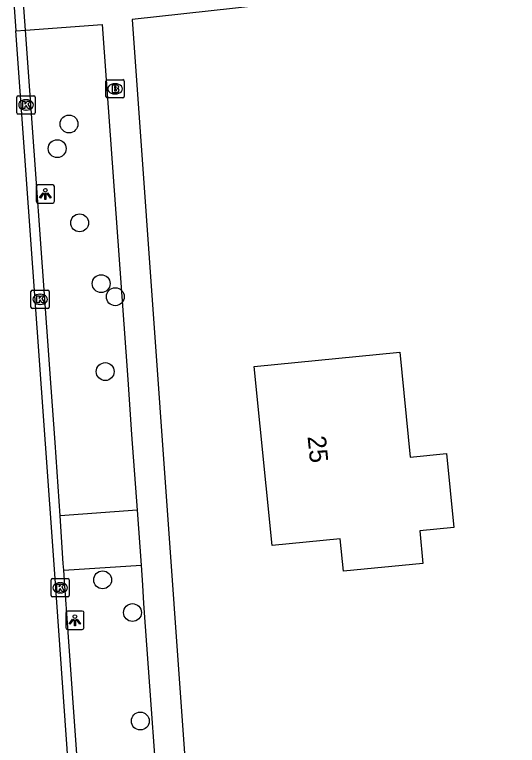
# Model space of a CAD drawing. Extents: x 162675 to 163482, y 379761 to 381227.
# Drawn here: x 163035.64 to 163063.15, y 380547.27 to 380587.25 of the extents above; entities that cross this region are included whole.
import ezdxf

# ---------------------------------------------------------------- set-up
doc = ezdxf.new("R2010")
doc.units = 0
for name, color, linetype in [('IMGEO_Boom', 7, 'Continuous'), ('IMGEO_Brandkraan', 7, 'Continuous'), ('IMGEO_Kolk', 7, 'Continuous'), ('IMGEO_Lichtpunt', 7, 'Continuous'), ('IMGEO_Pand', 7, 'Continuous'), ('IMGEO_Pand_nummerreeks', 7, 'Continuous'), ('IMGEO_Rijbaan_lokaal_gesloten', 7, 'Continuous'), ('IMGEO_Rijbaan_lokaal_open', 7, 'Continuous'), ('IMGEO_Voetpad_open', 7, 'Continuous')]:
    doc.layers.add(name, color=color, linetype=linetype)

msp = doc.modelspace()

# ---------------------------------------------------------------- linework, layer by layer
at = {"layer": 'IMGEO_Boom'}
for centre in [(163038.615, 380581.27), (163037.97, 380579.92), (163039.195, 380575.86), (163040.374, 380572.534), (163041.148, 380571.818), (163040.597, 380567.724), (163040.456, 380556.328), (163042.088, 380554.54), (163042.515, 380548.606)]:
    msp.add_circle(centre, 0.489, dxfattribs=at)
at = {"layer": 'IMGEO_Brandkraan'}
for p, q in [((163040.635, 380582.767), (163040.635, 380583.619)), ((163040.71, 380583.693), (163041.562, 380583.693)), ((163041.123, 380583.473), (163041.148, 380583.473)), ((163041.636, 380583.619), (163041.636, 380582.767)), ((163041.146, 380582.913), (163041.121, 380582.913)), ((163041.562, 380582.693), (163040.71, 380582.693))]:
    msp.add_line(p, q, dxfattribs=at)
for points in [[(163040.635, 380582.767), (163040.635, 380583.619)], [(163040.71, 380583.693), (163041.562, 380583.693)], [(163040.983, 380583.393), (163040.983, 380582.993), (163041.196, 380582.993)], [(163041.214, 380583.393), (163040.983, 380583.393)], [(163041.162, 380583.312), (163041.108, 380583.312), (163041.108, 380583.236)], [(163041.636, 380583.619), (163041.636, 380582.767)], [(163041.108, 380583.236), (163041.161, 380583.236)], [(163041.17, 380583.16), (163041.108, 380583.16), (163041.108, 380583.079)], [(163041.108, 380583.079), (163041.17, 380583.079)], [(163041.562, 380582.693), (163040.71, 380582.693)]]:
    msp.add_lwpolyline(points, dxfattribs=at)
for centre, radius, start, end in [((163040.712, 380583.617), 0.0765, 91.552, 178.448), ((163040.712, 380583.617), 0.0765, 91.552, 178.448), ((163041.163, 380583.274), 0.0379, 267.8285, 90.9355), ((163041.218, 380583.248), 0.145, 59.4692, 91.5367), ((163041.243, 380583.295), 0.0922, 285.5137, 58.1501), ((163041.56, 380583.617), 0.0765, 1.552, 88.448), ((163041.56, 380583.617), 0.0765, 1.552, 88.448), ((163041.171, 380583.119), 0.0404, 269.8759, 90.5077), ((163041.202, 380583.244), 0.251, 268.6676, 293.5347), ((163041.248, 380583.103), 0.105, 301.3115, 78.989), ((163040.712, 380582.769), 0.0765, 181.552, 268.448), ((163040.712, 380582.769), 0.0765, 181.552, 268.448), ((163041.56, 380582.769), 0.0765, 271.552, 358.448), ((163041.56, 380582.769), 0.0765, 271.552, 358.448)]:
    msp.add_arc(centre, radius, start, end, dxfattribs=at)
for centre, major_axis, ratio, start_param, end_param in [((163041.122, 380583.193), (-0.387, 0.002), 0.722429, 4.712389, 7.853982), ((163041.147, 380583.193), (-0.39, 0.002), 0.717154, 1.570796, 4.712389)]:
    msp.add_ellipse(centre, major_axis=major_axis, ratio=ratio, start_param=start_param, end_param=end_param, dxfattribs=at)
at = {"layer": 'IMGEO_Kolk'}
for p, q in [((163035.762, 380581.887), (163035.762, 380582.739)), ((163035.837, 380582.813), (163036.689, 380582.813)), ((163036.25, 380582.593), (163036.275, 380582.593)), ((163036.763, 380582.739), (163036.763, 380581.887)), ((163036.689, 380581.813), (163035.837, 380581.813)), ((163036.273, 380582.033), (163036.248, 380582.033)), ((163036.609, 380572.176), (163037.461, 380572.176)), ((163036.534, 380571.25), (163036.534, 380572.102)), ((163037.022, 380571.956), (163037.047, 380571.956)), ((163037.535, 380572.102), (163037.535, 380571.25)), ((163037.045, 380571.396), (163037.02, 380571.396)), ((163037.461, 380571.176), (163036.609, 380571.176)), ((163037.63, 380555.47), (163037.63, 380556.322)), ((163037.705, 380556.396), (163038.557, 380556.396)), ((163038.118, 380556.176), (163038.143, 380556.176)), ((163038.631, 380556.322), (163038.631, 380555.47)), ((163038.557, 380555.396), (163037.705, 380555.396)), ((163038.141, 380555.616), (163038.116, 380555.616))]:
    msp.add_line(p, q, dxfattribs=at)
for points in [[(163035.762, 380581.887), (163035.762, 380582.739)], [(163035.837, 380582.813), (163036.689, 380582.813)], [(163036.083, 380582.513), (163036.206, 380582.513), (163036.206, 380582.362), (163036.336, 380582.513), (163036.5, 380582.513), (163036.354, 380582.362), (163036.507, 380582.113), (163036.355, 380582.113), (163036.27, 380582.277), (163036.206, 380582.21), (163036.206, 380582.113), (163036.083, 380582.113), (163036.083, 380582.513)], [(163036.763, 380582.739), (163036.763, 380581.887)], [(163036.689, 380581.813), (163035.837, 380581.813)], [(163036.609, 380572.176), (163037.461, 380572.176)], [(163036.534, 380571.25), (163036.534, 380572.102)], [(163036.855, 380571.876), (163036.978, 380571.876), (163036.978, 380571.725), (163037.108, 380571.876), (163037.272, 380571.876), (163037.126, 380571.725), (163037.279, 380571.476), (163037.127, 380571.476), (163037.042, 380571.64), (163036.978, 380571.573), (163036.978, 380571.476), (163036.855, 380571.476), (163036.855, 380571.876)], [(163037.535, 380572.102), (163037.535, 380571.25)], [(163037.461, 380571.176), (163036.609, 380571.176)], [(163037.63, 380555.47), (163037.63, 380556.322)], [(163037.705, 380556.396), (163038.557, 380556.396)], [(163038.631, 380556.322), (163038.631, 380555.47)], [(163037.951, 380556.096), (163038.074, 380556.096), (163038.074, 380555.945), (163038.204, 380556.096), (163038.368, 380556.096), (163038.222, 380555.945), (163038.375, 380555.696), (163038.223, 380555.696), (163038.138, 380555.86), (163038.074, 380555.793), (163038.074, 380555.696), (163037.951, 380555.696), (163037.951, 380556.096)], [(163038.557, 380555.396), (163037.705, 380555.396)]]:
    msp.add_lwpolyline(points, dxfattribs=at)
for centre, start, end in [((163035.839, 380582.737), 91.552, 178.448), ((163035.839, 380582.737), 91.552, 178.448), ((163036.687, 380582.737), 1.552, 88.448), ((163036.687, 380582.737), 1.552, 88.448), ((163035.839, 380581.889), 181.552, 268.448), ((163035.839, 380581.889), 181.552, 268.448), ((163036.687, 380581.889), 271.552, 358.448), ((163036.687, 380581.889), 271.552, 358.448), ((163036.611, 380572.1), 91.552, 178.448), ((163036.611, 380572.1), 91.552, 178.448), ((163037.459, 380572.1), 1.552, 88.448), ((163037.459, 380572.1), 1.552, 88.448), ((163036.611, 380571.252), 181.552, 268.448), ((163036.611, 380571.252), 181.552, 268.448), ((163037.459, 380571.252), 271.552, 358.448), ((163037.459, 380571.252), 271.552, 358.448), ((163037.707, 380556.32), 91.552, 178.448), ((163037.707, 380556.32), 91.552, 178.448), ((163038.555, 380556.32), 1.552, 88.448), ((163038.555, 380556.32), 1.552, 88.448), ((163037.707, 380555.472), 181.552, 268.448), ((163037.707, 380555.472), 181.552, 268.448), ((163038.555, 380555.472), 271.552, 358.448), ((163038.555, 380555.472), 271.552, 358.448)]:
    msp.add_arc(centre, 0.0765, start, end, dxfattribs=at)
for centre, major_axis, ratio, start_param, end_param in [((163036.249, 380582.313), (-0.387, 0.002), 0.722429, 4.712389, 7.853982), ((163036.274, 380582.313), (-0.39, 0.002), 0.717154, 1.570796, 4.712389), ((163037.021, 380571.676), (-0.387, 0.002), 0.722429, 4.712389, 7.853982), ((163037.046, 380571.676), (-0.39, 0.002), 0.717154, 1.570796, 4.712389), ((163038.117, 380555.896), (-0.387, 0.002), 0.722429, 4.712389, 7.853982), ((163038.142, 380555.896), (-0.39, 0.002), 0.717154, 1.570796, 4.712389)]:
    msp.add_ellipse(centre, major_axis=major_axis, ratio=ratio, start_param=start_param, end_param=end_param, dxfattribs=at)
at = {"layer": 'IMGEO_Lichtpunt'}
for p, q in [((163036.822, 380577.845), (163036.822, 380577.038)), ((163036.822, 380577.845), (163036.822, 380577.038)), ((163037.724, 380577.94), (163036.916, 380577.94)), ((163037.724, 380577.94), (163036.916, 380577.94)), ((163037.818, 380577.038), (163037.818, 380577.845)), ((163037.818, 380577.038), (163037.818, 380577.845)), ((163036.916, 380576.944), (163037.724, 380576.944)), ((163036.916, 380576.944), (163037.724, 380576.944)), ((163038.439, 380554.524), (163038.439, 380553.717)), ((163038.439, 380554.524), (163038.439, 380553.717)), ((163039.341, 380554.619), (163038.533, 380554.619)), ((163039.341, 380554.619), (163038.533, 380554.619)), ((163039.435, 380553.717), (163039.435, 380554.524)), ((163039.435, 380553.717), (163039.435, 380554.524)), ((163038.533, 380553.623), (163039.341, 380553.623)), ((163038.533, 380553.623), (163039.341, 380553.623))]:
    msp.add_line(p, q, dxfattribs=at)
for points in [[(163037.196, 380577.509), (163037.235, 380577.481), (163037.047, 380577.219), (163037.009, 380577.246), (163037.196, 380577.509)], [(163037.298, 380577.461), (163037.345, 380577.461), (163037.345, 380577.139), (163037.298, 380577.139), (163037.298, 380577.461)], [(163037.408, 380577.481), (163037.446, 380577.508), (163037.633, 380577.246), (163037.594, 380577.218), (163037.408, 380577.481)], [(163038.813, 380554.188), (163038.852, 380554.16), (163038.664, 380553.898), (163038.626, 380553.925), (163038.813, 380554.188)], [(163038.915, 380554.14), (163038.962, 380554.14), (163038.962, 380553.818), (163038.915, 380553.818), (163038.915, 380554.14)], [(163039.025, 380554.16), (163039.063, 380554.187), (163039.25, 380553.925), (163039.211, 380553.897), (163039.025, 380554.16)]]:
    msp.add_lwpolyline(points, dxfattribs=at)
for centre in [(163037.321, 380577.643), (163038.938, 380554.322)]:
    msp.add_circle(centre, 0.0994, dxfattribs=at)
for centre, start, end in [((163036.916, 380577.845), 90, 180), ((163036.916, 380577.845), 90, 180), ((163037.724, 380577.845), 0, 90), ((163037.724, 380577.845), 0, 90), ((163036.916, 380577.038), 180, 270), ((163036.916, 380577.038), 180, 270), ((163037.724, 380577.038), 270, 0), ((163037.724, 380577.038), 270, 360), ((163038.533, 380554.524), 90, 180), ((163038.533, 380554.524), 90, 180), ((163039.341, 380554.524), 0, 90), ((163039.341, 380554.524), 0, 90), ((163038.533, 380553.717), 180, 270), ((163038.533, 380553.717), 180, 270), ((163039.341, 380553.717), 270, 0), ((163039.341, 380553.717), 270, 360)]:
    msp.add_arc(centre, 0.0946, start, end, dxfattribs=at)
at = {"layer": 'IMGEO_Pand'}
msp.add_lwpolyline([(163057.286, 380563.044), (163059.267, 380563.241), (163059.669, 380559.19), (163057.807, 380559.005), (163057.982, 380557.233), (163053.633, 380556.801), (163053.457, 380558.574), (163049.726, 380558.204), (163048.754, 380567.994), (163056.716, 380568.784), (163057.286, 380563.044)], dxfattribs=at)
at = {"layer": 'IMGEO_Rijbaan_lokaal_gesloten'}
for points in [[(163022.107, 380776.024), (163022.717, 380767.964), (163035.712, 380586.364)], [(163045.357, 380450.111), (163037.801, 380557.176), (163035.712, 380586.364)]]:
    msp.add_lwpolyline(points, dxfattribs=at)
at = {"layer": 'IMGEO_Rijbaan_lokaal_open'}
for points in [[(163036.238, 380586.402), (163036.113, 380588.143)], [(163035.712, 380586.364), (163036.238, 380586.402)], [(163038.126, 380559.836), (163037.854, 380563.848), (163037.639, 380566.853), (163036.238, 380586.402)], [(163038.328, 380556.861), (163038.303, 380557.221), (163038.126, 380559.836)], [(163039.456, 380540.911), (163038.478, 380554.744), (163038.46, 380555.004), (163038.407, 380555.75), (163038.328, 380556.861)]]:
    msp.add_lwpolyline(points, dxfattribs=at)
at = {"layer": 'IMGEO_Voetpad_open'}
for points in [[(163070.867, 380590.166), (163070.497, 380590.125), (163042.074, 380586.977), (163046.628, 380523.045), (163076.447, 380526.277)], [(163036.238, 380586.402), (163040.428, 380586.713), (163041.825, 380567.294), (163042.042, 380564.28), (163042.339, 380560.146)], [(163042.339, 380560.146), (163038.126, 380559.836)], [(163042.339, 380560.146), (163042.557, 380557.127)], [(163038.328, 380556.861), (163042.557, 380557.127)], [(163042.557, 380557.127), (163042.635, 380556.036), (163042.7, 380555.033), (163043.696, 380541.217)]]:
    msp.add_lwpolyline(points, dxfattribs=at)

# ---------------------------------------------------------------- texts
at = {"layer": 'IMGEO_Pand_nummerreeks'}
msp.add_text('25', height=1, rotation=275.6663, dxfattribs=at).set_placement((163051.666, 380564.171))

doc.saveas('drawing.dxf')
